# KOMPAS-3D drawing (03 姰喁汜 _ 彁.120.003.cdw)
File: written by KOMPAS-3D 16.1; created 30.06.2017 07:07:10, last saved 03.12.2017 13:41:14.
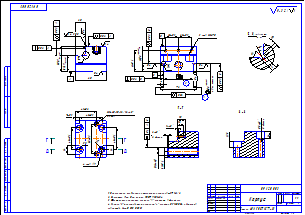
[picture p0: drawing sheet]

Sheet 1: A2, landscape

Title block, sheet 1: name: Корпус; designation: ПР.120.003; material: Сталь 40Х ГОСТ 1577-81; scale: 1:1; sheets: 1; sheet format: A2; stored path: D:\VSE\Эрга\Оснастка\Гибка лепестков\Прохвост\Корпус _ К17.479.003.cdw; drawn by: Сигачев СИ

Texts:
  Sergey
  с 2-х сторон
  Е, Ж (повернуто)
  М8-6Нх10х12/1,6х45
  Стандартные изделия
  Отверстие М8x8-10/1,6x45°
  Неуказанные предельные отклонения размеров  (IT 14)/2.
  Покрытие: Хим. Окс. прм по ГОСТ 9.303-84.
  Фактическое значение размера "в" записать в формуляр.
  Размер "б" согласовать с размером "а" корпуса ПР.120.004, обеспечив
  равенство б=а-(0,015...0,035).
  Ra3,2
  Ra3,2 ( )
  CONTINUOUS_RGB_0_0_255_THICK_0.18
  CONTINUOUS_RGB_0_255_0_THICK_0.18
  TypeKE
  KTE.LIST=LTWD36N5dmSErgwNQxupvb
  ParamsKE
  float
Dimensions and other numbers on the sheet: 0,4; 60; 20; 0,5; 0,02; 32; 50; 7; 58±0,2; 15; 41±0,1; 72; 25±0,1; 3 отв.; 5-7Н; 1,6; 2; 4 отв.; 9; 43±0,1; 16; 45; 1; 12±0,1; 2 фаски; -6Н; 0,1; 12,5; 14; 8 фасок; 8; 2 отв.; 1.6; 6.64683530658681; 7.18810118395209; 1.25; 0; 118; 10; 1:1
